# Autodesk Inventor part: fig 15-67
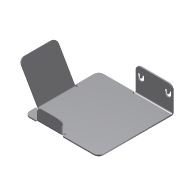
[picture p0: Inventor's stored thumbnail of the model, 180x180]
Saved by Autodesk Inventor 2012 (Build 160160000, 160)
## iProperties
Shininess: 77.0
Angle Display Precision: 2
Document Length Units: 11269
Document Angle Units: 11279
Document Time Units: 11290
Document Mass Units: 11283
Document Length Units Precision: 3
Document Angle Units Precision: 2
Created: 2002-04
Part Number: fig 15-67
Document SubType Name: Sheet Metal
Density: 1 g/cm^3
Sheet Metal Rule: Default
Material: Default
Density: 0.0
Volumn: 0.0
Area: 0.0
PropertySet Name: Model Information
Control State: 0
Master: False
Checked Out: False
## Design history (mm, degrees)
node "Face1"
  sketch "Sketch1"
    geometry: L1 (12.647, 25.882)-(12.647, -14.118); L2 (12.647, -14.118)-(-17.353, -14.118); L3 (-17.353, -14.118)-(-17.353, 15.882); L4 (-17.353, 15.882)-(-2.353, 15.882); L5 (-2.353, 15.882)-(-2.353, 25.882); L6 (-2.353, 25.882)-(12.647, 25.882); 1 further point
    constraints: 12 end point, 4 parallel, 1 perpendicular
    dimensions: "d5" = 30 distance of L2.end L3.end; "d6" = 10 distance of L4.end L5.end; "d7" = 15 distance of L3.end L4.end; "d25" = 15 distance of L5.end L1.start
sketch "Sketch3"
  geometry: L1 (10, -15)-(10, 0)
  constraints: 2 end point
feature "Fold3" sketch "Sketch3" dims "d26" = 0.5 (= BendRadius), "d27" = 90 deg, "d28" = 0.5 (= BendRadius), "d96" = 0.5 (= BendReliefWidth), "d97" = 0.25 (= BendReliefDepth), "d98" = 1 (= MinimumRemnant), "SeamGap" = 0.01, "Thickness" = 0.5
node "Flange2"
sketch "Sketch6"
  geometry: L1 (-6.914, 3.413)-(-5.843, 3.413); L2 (-5.843, 0.624)-(-6.914, 0.624); L3 (-6.914, 2.432)-(-5.843, 2.432); L4 (-5.843, 1.605)-(-6.914, 1.605); L5 (-6.914, 0.624)-(-6.914, 1.605); L6 (-6.914, 2.432)-(-6.914, 3.413); L7 (-6.914, 12.568)-(-6.914, 11.587); L8 (-6.914, 14.376)-(-6.914, 13.395); L9 (-6.914, 11.587)-(-5.843, 11.587); L10 (-5.843, 14.376)-(-6.914, 14.376); L11 (-6.914, 12.568)-(-5.843, 12.568); L12 (-5.843, 13.395)-(-6.914, 13.395); A1 r 1.394 centre (-5.843, 2.018) between (-5.843, 0.624) and (-5.843, 3.413); A2 r 0.413 centre (-5.843, 2.018) between (-5.843, 1.605) and (-5.843, 2.432); A3 r 1.394 centre (-5.843, 12.982) between (-5.843, 11.587) and (-5.843, 14.376); A4 r 0.413 centre (-5.843, 12.982) between (-5.843, 12.568) and (-5.843, 13.395)
  constraints: 24 end point, 8 point on circle, 4 centre point, 3 equal length, 1 perpendicular
cut "Cut1" sketch "Sketch6" dims "d49" = 0.5 (= Thickness), "d50" = 0
node "Flange3"
feature "Corner Round2" dims "d107" = 2
body "Solid1"
face "Plate1" dims "Thickness" = 0.5
sketch "Sketch5"
  geometry: L1 (20, 0)-(5, 0); L2 (5, 0)-(5, 15); L3 (5, 15)-(20, 15); L4 (20, 15)-(20, 0)
  constraints: 8 end point
face "Plate6" dims "d35" = 10, "d36" = 5, "d38" = 15, "d39" = 60 deg, "d40" = 0.5 (= BendRadius), "Thickness" = 0.5, "MinimumRemnant" = 1 (= 2 x Thickness), "BendReliefWidth" = 0.5 (= Thickness)
bend "Bend5" dims "d38" = 15, "d39" = 60 deg, "d40" = 0.5 (= BendRadius), "d99" = 0.5 (= BendReliefWidth), "d100" = 0.25 (= BendReliefDepth), "d101" = 1 (= MinimumRemnant), "SeamGap" = 0.01, "Thickness" = 0.5, "MinimumRemnant" = 1 (= 2 x Thickness), "BendReliefWidth" = 0.5 (= Thickness), "TransitionRadius" = 0.5 (= BendRadius)
sketch "Sketch7"
  geometry: L1 (25, 0)-(15, 0); L2 (15, 0)-(15, 5); L3 (15, 5)-(25, 5); L4 (25, 5)-(25, 0)
  constraints: 8 end point
face "Plate7" dims "d57" = 5, "d58" = 10, "d60" = 5, "d61" = 90 deg, "d62" = 0.5 (= BendRadius), "Thickness" = 0.5, "MinimumRemnant" = 1 (= 2 x Thickness), "BendReliefWidth" = 0.5 (= Thickness)
bend "Bend7" dims "d59" = 0.5 (= BendRadius), "d60" = 5, "d61" = 90 deg, "d62" = 0.5 (= BendRadius), "d102" = 0.5 (= BendReliefWidth), "d103" = 0.25 (= BendReliefDepth), "d104" = 1 (= MinimumRemnant), "SeamGap" = 0.01, "Thickness" = 0.5, "MinimumRemnant" = 1 (= 2 x Thickness), "BendReliefWidth" = 0.5 (= Thickness)
other parameters: "BendRadius" = 0.5 (= Thickness), "BendReliefDepth" = 0.25 (= 0.5 x Thickness), "CornerReliefSize" = 2 (= 4 x Thickness), "d0" = 0.5 (= BendRadius), "d13" = 0.5 (= BendRadius), "d31" = 0.5 (= BendRadius), "d37" = 0.5 (= BendRadius), "JacobiRadiusSize" = 0.5 (= Thickness), "GapSize" = 0.5 (= Thickness)
